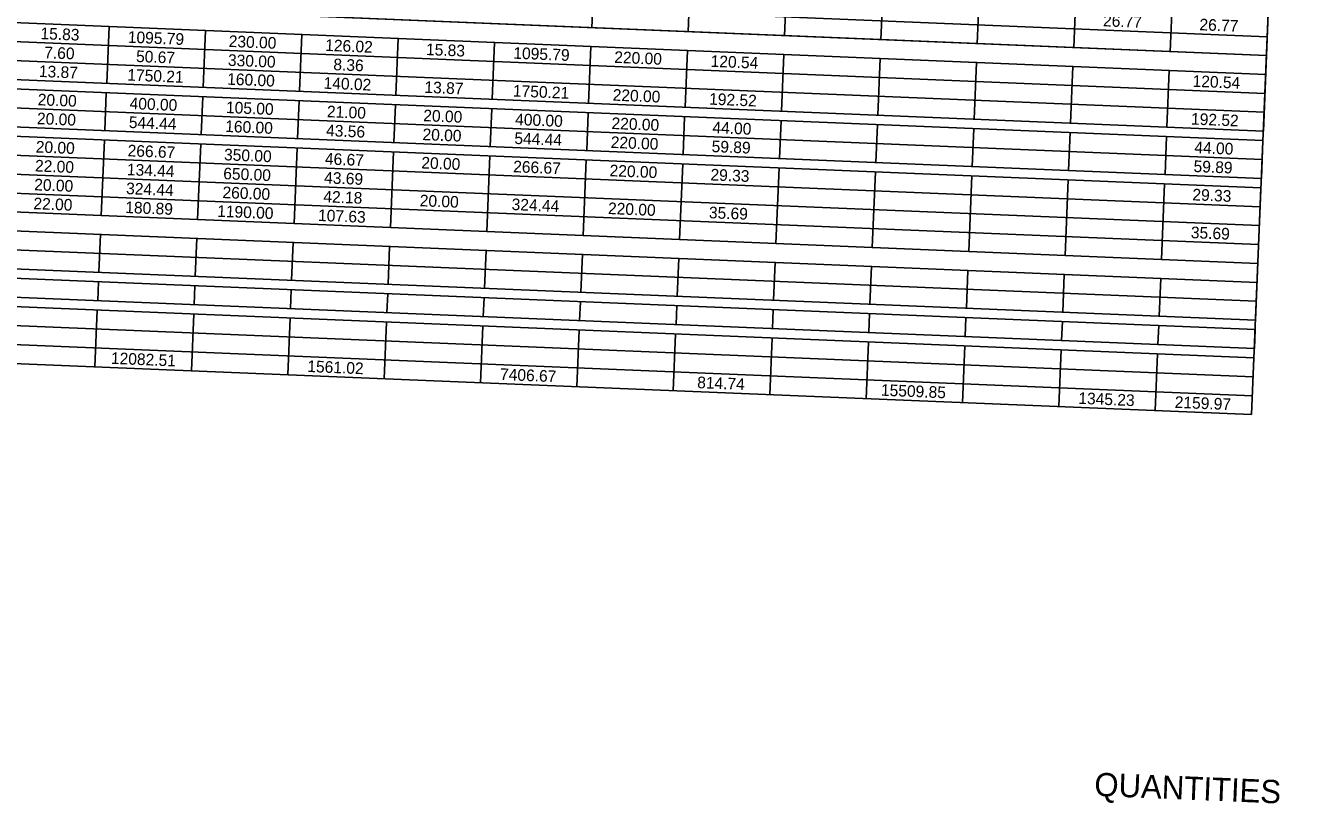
# Model space of a CAD drawing. Extents: x 1164179 to 1171425, y 1655958 to 1657208.
# Drawn here: x 1168859 to 1169513, y 1656035 to 1656436 of the extents above; entities that cross this region are included whole.
import ezdxf

# ---------------------------------------------------------------- set-up
doc = ezdxf.new("R2010")
doc.units = 0
doc.layers.add('Default', color=7, linetype='Continuous')
doc.layers.add('R_Border Prem', color=7, linetype='Continuous')

msp = doc.modelspace()

# ---------------------------------------------------------------- linework, layer by layer
at = {"layer": 'Default'}
for p, q in [((1169491.27, 1656235.62), (1169513.44, 1656771.41)), ((1168012.27, 1656491.97), (1169499.33, 1656430.45)), ((1168011.87, 1656482.23), (1169498.93, 1656420.71)), ((1168011.46, 1656472.49), (1169498.53, 1656410.97)), ((1169151.15, 1656435.1), (1169152.77, 1656474.06)), ((1169151.15, 1656435.1), (1169152.77, 1656474.06)), ((1169200.84, 1656433.04), (1169202.45, 1656472.01)), ((1169200.84, 1656433.04), (1169202.45, 1656472.01)), ((1169250.52, 1656430.99), (1169252.13, 1656469.95)), ((1169250.52, 1656430.99), (1169252.13, 1656469.95)), ((1169300.2, 1656428.93), (1169301.81, 1656467.9)), ((1169300.2, 1656428.93), (1169301.81, 1656467.9)), ((1169349.88, 1656426.88), (1169351.5, 1656465.84)), ((1169349.88, 1656426.88), (1169351.5, 1656465.84)), ((1169399.57, 1656424.82), (1169401.18, 1656463.79)), ((1169399.57, 1656424.82), (1169401.18, 1656463.79)), ((1168011.06, 1656462.74), (1169498.13, 1656401.23)), ((1169449.25, 1656422.77), (1169450.86, 1656461.73)), ((1169449.25, 1656422.77), (1169450.86, 1656461.73)), ((1169497.32, 1656381.74), (1169500.54, 1656459.68)), ((1168010.66, 1656453), (1169497.72, 1656391.49)), ((1168853.06, 1656447.43), (1169300.2, 1656428.93)), ((1168010.05, 1656438.39), (1169497.12, 1656376.87)), ((1168010.25, 1656443.26), (1169497.32, 1656381.74)), ((1168901.13, 1656406.41), (1168902.34, 1656435.63)), ((1168901.13, 1656406.41), (1168902.34, 1656435.63)), ((1168950.81, 1656404.35), (1168952.02, 1656433.58)), ((1168950.81, 1656404.35), (1168952.02, 1656433.58)), ((1169000.49, 1656402.3), (1169001.7, 1656431.52)), ((1169000.49, 1656402.3), (1169001.7, 1656431.52)), ((1168009.65, 1656428.65), (1169496.72, 1656367.13)), ((1168354.62, 1656429.02), (1169497.32, 1656381.74)), ((1169050.18, 1656400.24), (1169051.39, 1656429.47)), ((1169050.18, 1656400.24), (1169051.39, 1656429.47)), ((1169099.86, 1656398.19), (1169101.07, 1656427.41)), ((1169099.86, 1656398.19), (1169101.07, 1656427.41)), ((1169149.54, 1656396.13), (1169150.75, 1656425.36)), ((1169149.54, 1656396.13), (1169150.75, 1656425.36)), ((1169300.2, 1656428.93), (1169349.88, 1656426.88)), ((1169349.88, 1656426.88), (1169449.25, 1656422.77)), ((1168009.25, 1656418.91), (1169496.31, 1656357.39)), ((1169199.22, 1656394.08), (1169200.43, 1656423.3)), ((1169199.22, 1656394.08), (1169200.43, 1656423.3)), ((1169248.91, 1656392.02), (1169250.12, 1656421.25)), ((1169248.91, 1656392.02), (1169250.12, 1656421.25)), ((1169298.59, 1656389.96), (1169299.8, 1656419.19)), ((1169298.59, 1656389.96), (1169299.8, 1656419.19)), ((1169449.25, 1656422.77), (1169498.93, 1656420.71)), ((1168009.05, 1656414.04), (1169496.11, 1656352.52)), ((1169348.27, 1656387.91), (1169349.48, 1656417.13)), ((1169348.27, 1656387.91), (1169349.48, 1656417.13)), ((1169397.95, 1656385.85), (1169399.16, 1656415.08)), ((1169397.95, 1656385.85), (1169399.16, 1656415.08)), ((1169447.64, 1656383.8), (1169448.85, 1656413.02)), ((1169447.64, 1656383.8), (1169448.85, 1656413.02)), ((1168353.61, 1656404.66), (1169496.31, 1656357.39)), ((1168008.64, 1656404.29), (1169495.71, 1656342.78)), ((1168900.12, 1656382.05), (1168900.93, 1656401.54)), ((1168900.12, 1656382.05), (1168900.93, 1656401.54)), ((1168949.8, 1656380), (1168950.61, 1656399.48)), ((1168949.8, 1656380), (1168950.61, 1656399.48)), ((1168008.24, 1656394.55), (1169495.3, 1656333.04)), ((1168999.49, 1656377.94), (1169000.29, 1656397.43)), ((1168999.49, 1656377.94), (1169000.29, 1656397.43)), ((1169049.17, 1656375.89), (1169049.98, 1656395.37)), ((1169049.17, 1656375.89), (1169049.98, 1656395.37)), ((1169098.85, 1656373.83), (1169099.66, 1656393.32)), ((1169098.85, 1656373.83), (1169099.66, 1656393.32)), ((1169148.53, 1656371.78), (1169149.34, 1656391.26)), ((1169148.53, 1656371.78), (1169149.34, 1656391.26)), ((1169198.22, 1656369.72), (1169199.02, 1656389.2)), ((1169198.22, 1656369.72), (1169199.02, 1656389.2)), ((1169247.9, 1656367.67), (1169248.71, 1656387.15)), ((1169247.9, 1656367.67), (1169248.71, 1656387.15)), ((1169297.58, 1656365.61), (1169298.39, 1656385.09)), ((1169297.58, 1656365.61), (1169298.39, 1656385.09)), ((1168007.84, 1656384.81), (1169494.9, 1656323.29)), ((1169347.26, 1656363.56), (1169348.07, 1656383.04)), ((1169347.26, 1656363.56), (1169348.07, 1656383.04)), ((1169396.95, 1656361.5), (1169397.75, 1656380.98)), ((1169396.95, 1656361.5), (1169397.75, 1656380.98)), ((1169446.63, 1656359.44), (1169447.44, 1656378.93)), ((1169446.63, 1656359.44), (1169447.44, 1656378.93)), ((1168007.43, 1656375.07), (1169494.5, 1656313.55)), ((1168007.43, 1656375.07), (1169494.5, 1656313.55)), ((1168898.31, 1656338.22), (1168899.92, 1656377.18)), ((1168898.31, 1656338.22), (1168899.92, 1656377.18)), ((1168947.99, 1656336.16), (1168949.6, 1656375.13)), ((1168947.99, 1656336.16), (1168949.6, 1656375.13)), ((1168997.67, 1656334.1), (1168999.29, 1656373.07)), ((1168997.67, 1656334.1), (1168999.29, 1656373.07)), ((1169496.31, 1656357.39), (1169497.12, 1656376.87)), ((1169047.36, 1656332.05), (1169048.97, 1656371.02)), ((1169047.36, 1656332.05), (1169048.97, 1656371.02)), ((1169097.04, 1656329.99), (1169098.65, 1656368.96)), ((1169097.04, 1656329.99), (1169098.65, 1656368.96)), ((1169146.72, 1656327.94), (1169148.33, 1656366.91)), ((1169146.72, 1656327.94), (1169148.33, 1656366.91)), ((1168007.03, 1656365.33), (1169494.1, 1656303.81)), ((1169196.4, 1656325.88), (1169198.02, 1656364.85)), ((1169196.4, 1656325.88), (1169198.02, 1656364.85)), ((1169246.09, 1656323.83), (1169247.7, 1656362.8)), ((1169246.09, 1656323.83), (1169247.7, 1656362.8)), ((1169295.77, 1656321.77), (1169297.38, 1656360.74)), ((1169295.77, 1656321.77), (1169297.38, 1656360.74)), ((1168006.63, 1656355.59), (1169493.69, 1656294.07)), ((1169345.45, 1656319.72), (1169347.06, 1656358.68)), ((1169345.45, 1656319.72), (1169347.06, 1656358.68)), ((1169395.13, 1656317.66), (1169396.75, 1656356.63)), ((1169395.13, 1656317.66), (1169396.75, 1656356.63)), ((1169444.82, 1656315.61), (1169446.43, 1656354.57)), ((1169444.82, 1656315.61), (1169446.43, 1656354.57)), ((1169493.29, 1656284.33), (1169496.11, 1656352.52)), ((1168006.22, 1656345.84), (1169493.29, 1656284.33)), ((1168006.02, 1656340.97), (1169493.09, 1656279.46)), ((1168005.42, 1656326.36), (1169492.48, 1656264.84)), ((1168005.62, 1656331.23), (1169492.69, 1656269.71)), ((1168350.59, 1656331.6), (1169493.29, 1656284.33)), ((1168897.1, 1656308.99), (1168897.91, 1656328.47)), ((1168897.1, 1656308.99), (1168897.91, 1656328.47)), ((1168946.78, 1656306.94), (1168947.59, 1656326.42)), ((1168946.78, 1656306.94), (1168947.59, 1656326.42)), ((1168996.46, 1656304.88), (1168997.27, 1656324.36)), ((1168996.46, 1656304.88), (1168997.27, 1656324.36)), ((1169046.15, 1656302.82), (1169046.95, 1656322.31)), ((1169046.15, 1656302.82), (1169046.95, 1656322.31)), ((1169095.83, 1656300.77), (1169096.64, 1656320.25)), ((1169095.83, 1656300.77), (1169096.64, 1656320.25)), ((1168005.02, 1656316.62), (1169492.08, 1656255.1)), ((1168349.99, 1656316.99), (1169492.69, 1656269.71)), ((1169145.51, 1656298.71), (1169146.32, 1656318.2)), ((1169145.51, 1656298.71), (1169146.32, 1656318.2)), ((1169195.19, 1656296.66), (1169196, 1656316.14)), ((1169195.19, 1656296.66), (1169196, 1656316.14)), ((1169244.88, 1656294.6), (1169245.68, 1656314.09)), ((1169244.88, 1656294.6), (1169245.68, 1656314.09)), ((1168004.61, 1656306.88), (1169491.68, 1656245.36)), ((1169294.56, 1656292.55), (1169295.37, 1656312.03)), ((1169294.56, 1656292.55), (1169295.37, 1656312.03)), ((1169344.24, 1656290.49), (1169345.05, 1656309.98)), ((1169344.24, 1656290.49), (1169345.05, 1656309.98)), ((1169393.92, 1656288.44), (1169394.73, 1656307.92)), ((1169393.92, 1656288.44), (1169394.73, 1656307.92)), ((1168896.5, 1656294.38), (1168896.9, 1656304.12)), ((1168896.5, 1656294.38), (1168896.9, 1656304.12)), ((1168946.18, 1656292.32), (1168946.58, 1656302.06)), ((1168946.18, 1656292.32), (1168946.58, 1656302.06)), ((1168995.86, 1656290.27), (1168996.26, 1656300.01)), ((1168995.86, 1656290.27), (1168996.26, 1656300.01)), ((1169443.61, 1656286.38), (1169444.41, 1656305.87)), ((1169443.61, 1656286.38), (1169444.41, 1656305.87)), ((1168004.21, 1656297.14), (1169491.27, 1656235.62)), ((1169045.54, 1656288.21), (1169045.95, 1656297.95)), ((1169045.54, 1656288.21), (1169045.95, 1656297.95)), ((1169095.23, 1656286.16), (1169095.63, 1656295.9)), ((1169095.23, 1656286.16), (1169095.63, 1656295.9)), ((1169144.91, 1656284.1), (1169145.31, 1656293.84)), ((1169144.91, 1656284.1), (1169145.31, 1656293.84)), ((1168895.08, 1656260.28), (1168896.29, 1656289.51)), ((1168895.08, 1656260.28), (1168896.29, 1656289.51)), ((1168944.77, 1656258.23), (1168945.98, 1656287.45)), ((1168944.77, 1656258.23), (1168945.98, 1656287.45)), ((1169194.59, 1656282.05), (1169194.99, 1656291.79)), ((1169194.59, 1656282.05), (1169194.99, 1656291.79)), ((1169244.27, 1656279.99), (1169244.68, 1656289.73)), ((1169244.27, 1656279.99), (1169244.68, 1656289.73)), ((1169293.96, 1656277.94), (1169294.36, 1656287.68)), ((1169293.96, 1656277.94), (1169294.36, 1656287.68)), ((1168994.45, 1656256.17), (1168995.66, 1656285.4)), ((1168994.45, 1656256.17), (1168995.66, 1656285.4)), ((1169044.13, 1656254.12), (1169045.34, 1656283.34)), ((1169044.13, 1656254.12), (1169045.34, 1656283.34)), ((1169093.81, 1656252.06), (1169095.02, 1656281.29)), ((1169093.81, 1656252.06), (1169095.02, 1656281.29)), ((1169343.64, 1656275.88), (1169344.04, 1656285.62)), ((1169343.64, 1656275.88), (1169344.04, 1656285.62)), ((1169393.32, 1656273.83), (1169393.72, 1656283.57)), ((1169393.32, 1656273.83), (1169393.72, 1656283.57)), ((1169443, 1656271.77), (1169443.41, 1656281.51)), ((1169443, 1656271.77), (1169443.41, 1656281.51)), ((1169143.5, 1656250.01), (1169144.71, 1656279.23)), ((1169143.5, 1656250.01), (1169144.71, 1656279.23)), ((1169193.18, 1656247.95), (1169194.39, 1656277.18)), ((1169193.18, 1656247.95), (1169194.39, 1656277.18)), ((1169242.86, 1656245.9), (1169244.07, 1656275.12)), ((1169242.86, 1656245.9), (1169244.07, 1656275.12)), ((1169492.69, 1656269.71), (1169493.09, 1656279.46)), ((1169292.54, 1656243.84), (1169293.75, 1656273.06)), ((1169292.54, 1656243.84), (1169293.75, 1656273.06)), ((1169342.23, 1656241.78), (1169343.44, 1656271.01)), ((1169342.23, 1656241.78), (1169343.44, 1656271.01)), ((1169391.91, 1656239.73), (1169393.12, 1656268.95)), ((1169391.91, 1656239.73), (1169393.12, 1656268.95)), ((1169441.59, 1656237.67), (1169442.8, 1656266.9)), ((1169441.59, 1656237.67), (1169442.8, 1656266.9)), ((1169491.27, 1656235.62), (1169492.48, 1656264.84))]:
    msp.add_line(p, q, dxfattribs=at)

# ---------------------------------------------------------------- texts
for s, p in [('26.77', (1169414.6, 1656435.83)), ('26.77', (1169464.29, 1656433.78)), ('15.83', (1168866.89, 1656429.22)), ('1095.79', (1168911.91, 1656427.35)), ('230.00', (1168963.93, 1656425.2)), ('7.60', (1168868.82, 1656419.38)), ('126.02', (1169013.64, 1656423.15)), ('15.83', (1169065.62, 1656421)), ('1095.79', (1169110.64, 1656419.13)), ('50.67', (1168916.17, 1656417.42)), ('330.00', (1168963.53, 1656415.46)), ('8.36', (1169017.86, 1656413.21)), ('220.00', (1169162.66, 1656416.98)), ('120.54', (1169212.35, 1656414.93)), ('13.87', (1168866.08, 1656409.73)), ('1750.21', (1168911.69, 1656407.85)), ('160.00', (1168963.13, 1656405.72)), ('140.02', (1169012.83, 1656403.66)), ('13.87', (1169064.81, 1656401.51)), ('1750.21', (1169110.42, 1656399.63)), ('120.54', (1169460.76, 1656404.65)), ('20.00', (1168865.49, 1656395.12)), ('400.00', (1168912.84, 1656393.16)), ('220.00', (1169161.86, 1656397.5)), ('192.52', (1169211.56, 1656395.44)), ('105.00', (1168962.52, 1656391.11)), ('21.00', (1169014.53, 1656388.95)), ('20.00', (1169064.22, 1656386.9)), ('20.00', (1168865.08, 1656385.38)), ('544.44', (1168912.44, 1656383.42)), ('160.00', (1168962.12, 1656381.36)), ('43.56', (1169014.12, 1656379.21)), ('400.00', (1169111.57, 1656384.94)), ('220.00', (1169161.25, 1656382.89)), ('44.00', (1169213.26, 1656380.73)), ('192.52', (1169459.97, 1656385.17)), ('20.00', (1169063.81, 1656377.16)), ('544.44', (1169111.17, 1656375.2)), ('220.00', (1169160.85, 1656373.14)), ('20.00', (1168864.48, 1656370.77)), ('266.67', (1168911.82, 1656368.81)), ('350.00', (1168961.52, 1656366.75)), ('59.89', (1169212.85, 1656370.99)), ('44.00', (1169461.68, 1656370.46)), ('22.00', (1168864.08, 1656361.02)), ('46.67', (1169013.52, 1656364.6)), ('20.00', (1169063.21, 1656362.55)), ('266.67', (1169110.55, 1656360.59)), ('59.89', (1169461.26, 1656360.72)), ('134.44', (1168911.43, 1656359.07)), ('650.00', (1168961.11, 1656357.01)), ('43.69', (1169013.11, 1656354.86)), ('220.00', (1169160.25, 1656358.53)), ('29.33', (1169212.25, 1656356.38)), ('20.00', (1168863.67, 1656351.28)), ('324.44', (1168911.03, 1656349.32)), ('260.00', (1168960.71, 1656347.27)), ('22.00', (1168863.27, 1656341.54)), ('42.18', (1169012.71, 1656345.12)), ('20.00', (1169062.4, 1656343.06)), ('324.44', (1169109.76, 1656341.1)), ('29.33', (1169460.66, 1656346.1)), ('180.89', (1168910.61, 1656339.58)), ('1190.00', (1168957.98, 1656337.62)), ('107.63', (1169009.98, 1656335.47)), ('220.00', (1169159.44, 1656339.05)), ('35.69', (1169211.44, 1656336.9)), ('35.69', (1169459.85, 1656326.62)), ('12082.51', (1168903.22, 1656261.82)), ('1561.02', (1169004.45, 1656257.63)), ('7406.67', (1169103.79, 1656253.52)), ('814.74', (1169205.39, 1656249.32)), ('15509.85', (1169300.13, 1656245.4)), ('1345.23', (1169401.88, 1656241.19)), ('2159.97', (1169451.56, 1656239.14))]:
    msp.add_text(s, height=6, rotation=357.63112, dxfattribs=at).set_placement(p)
at = {"layer": 'R_Border Prem'}
msp.add_text('QUANTITIES', height=12, rotation=357.63112, dxfattribs=at).set_placement((1169410.02, 1656039.11))

doc.saveas('drawing.dxf')
